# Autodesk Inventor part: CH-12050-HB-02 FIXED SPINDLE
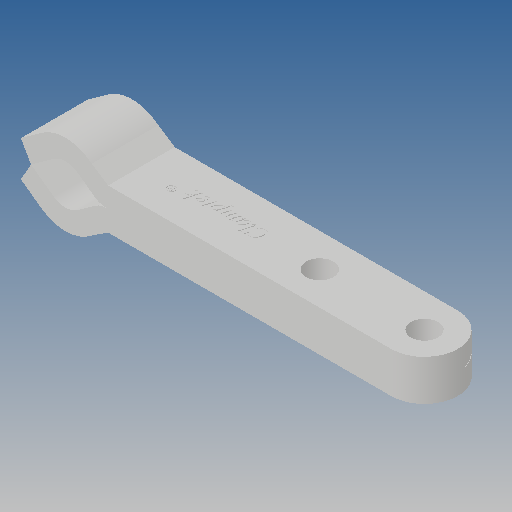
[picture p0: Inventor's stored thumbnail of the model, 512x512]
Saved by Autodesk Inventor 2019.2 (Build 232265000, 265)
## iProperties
Created: 2012-07
Part Number: CH-12050-HB-02 FIXED SPINDLE
Material: Ogólny
Document SubType Name: Modeling
Designer: CADENGINEERING4
Density: 1 g/cm^3
Appearance: Domyślna
Author: CADENGINEERING4
Revision Number: ÈÎºÎ
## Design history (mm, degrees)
feature "ÇÐ³ý-À­Éì2"
feature "ÇÐ³ý-À­Éì5"
node "Bryła1"
node "Bryła2"
